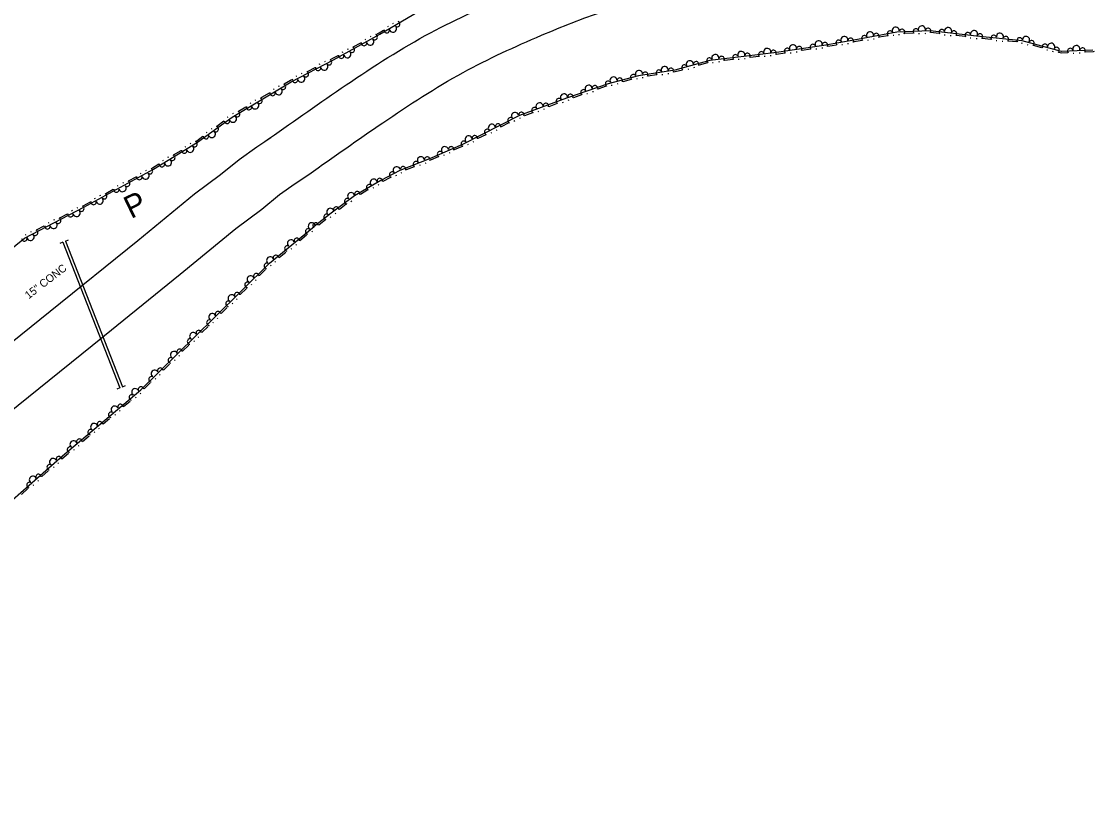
# Model space of a CAD drawing. Extents: x 2030130 to 2036320, y 723205 to 762423.
# Drawn here: x 2033977 to 2034480, y 760652 to 761017 of the extents above; entities that cross this region are included whole.
import ezdxf

# ---------------------------------------------------------------- set-up
doc = ezdxf.new("R2010")
doc.units = 0
for name, color, linetype in [('Draft_Station Labels Major', 7, 'Continuous'), ('Draft_Station Tics Major', 7, 'Continuous'), ('Draft_Station Tics Minor', 7, 'Continuous'), ('Old_Level_26', 7, 'Continuous'), ('Prop Horizontal Alignment Ramp', 7, 'Continuous')]:
    doc.layers.add(name, color=color, linetype=linetype)

msp = doc.modelspace()

# ---------------------------------------------------------------- linework, layer by layer
at = {"layer": 'Draft_Station Labels Major'}
for points in [[(2033869.46, 760774.27), (2033935.13, 760835.34), (2033990.71, 760880.07), (2034032.11, 760913.52), (2034058.88, 760935.52), (2034071.14, 760944.6), (2034079.83, 760951.72), (2034088.18, 760957.58), (2034094.76, 760962.04)], [(2033886.15, 760763.66), (2033955.13, 760819.42), (2034010.47, 760863.96), (2034051.97, 760897.49), (2034078.31, 760919.14), (2034090.56, 760928.21), (2034098.99, 760935.12), (2034106.37, 760940.3), (2034112.77, 760944.64)]]:
    msp.add_lwpolyline(points, dxfattribs=at)
for points in [[(2034092.04, 760960.15), (2034128.02, 760985.27), (2034167.72, 761010.14), (2034207.02, 761028.78), (2034238.75, 761041.08), (2034290.36, 761053.26), (2034339.84, 761057.27), (2034410.92, 761061), (2034496.35, 761063.49), (2034597.04, 761068.5), (2034676.22, 761073.92), (2034760.74, 761078.95), (2034860.07, 761085.08), (2034928.36, 761090.57)], [(2034112.77, 760944.64), (2034147.71, 760969.04), (2034185.56, 760992.74), (2034222.61, 761010.31), (2034251.75, 761021.61), (2034299.66, 761032.92), (2034346.78, 761036.74), (2034417.19, 761040.43), (2034502.59, 761042.92), (2034603.78, 761047.95), (2034683.1, 761053.38), (2034767.53, 761058.4), (2034867.13, 761064.56), (2034935.91, 761070.08)]]:
    msp.add_spline(points, degree=3, dxfattribs=at)
at = {"layer": 'Draft_Station Tics Major'}
for points in [[(2034091.07, 760980.33), (2034104.49, 760988.4), (2034124.48, 760998.73), (2034146.32, 761010.81), (2034166.94, 761022.97)], [(2034149.97, 761014.39), (2034150.32, 761014.6)], [(2034152.44, 761015.85), (2034152.8, 761016.06)], [(2034482.78, 761003.3), (2034468.01, 761002.71), (2034449.36, 761007.75), (2034427.83, 761009.88), (2034406.01, 761012.41), (2034390.26, 761011.73), (2034369.95, 761007.96), (2034355.78, 761005.54), (2034333.42, 761002.12), (2034318.05, 761000.34), (2034302.02, 760998.42), (2034285.55, 760993.78), (2034268.39, 760991.2), (2034254.03, 760987.44), (2034234.41, 760980.56), (2034212.25, 760972.4), (2034185.26, 760958.73), (2034169.68, 760952.03), (2034155.74, 760946.42), (2034146.7, 760941.76), (2034134.36, 760934.57), (2034123.31, 760926.27), (2034115.26, 760920)], [(2034141.81, 761009.72), (2034142.17, 761009.92)], [(2034144.52, 761010.75), (2034145.91, 761011.52), (2034148.06, 761012.79)], [(2034385.97, 761010.1), (2034381.93, 761009.35)], [(2034388.86, 761010.22), (2034388.46, 761010.15)], [(2034391.54, 761010.56), (2034391.12, 761010.54)], [(2034398.07, 761011.25), (2034393.97, 761011.07)], [(2034400.96, 761010.96), (2034400.55, 761010.94)], [(2034403.82, 761011.08), (2034403.42, 761011.06)], [(2034410.21, 761011.09), (2034406.14, 761011.57)], [(2034413.01, 761010.36), (2034412.61, 761010.4)], [(2034415.87, 761010.03), (2034415.46, 761010.07)], [(2034422.43, 761009.68), (2034418.36, 761010.15)], [(2034133.76, 761004.8), (2034137.35, 761006.78)], [(2034139.3, 761008.33), (2034139.66, 761008.53)], [(2034361.74, 761005.72), (2034357.7, 761005.03)], [(2034364.64, 761005.8), (2034364.24, 761005.73)], [(2034367.47, 761006.29), (2034367.06, 761006.22)], [(2034373.87, 761007.85), (2034370.09, 761007.15), (2034369.83, 761007.1)], [(2034376.77, 761007.97), (2034376.37, 761007.9)], [(2034379.59, 761008.5), (2034379.19, 761008.42)], [(2034425.23, 761008.94), (2034424.83, 761008.99)], [(2034428.11, 761008.61), (2034427.69, 761008.65), (2034427.66, 761008.66)], [(2034434.68, 761008.38), (2034430.6, 761008.78)], [(2034437.5, 761007.69), (2034437.09, 761007.73)], [(2034440.35, 761007.41), (2034439.94, 761007.45)], [(2034446.92, 761007.17), (2034442.84, 761007.57)], [(2034449.52, 761006.43), (2034449.13, 761006.54)], [(2034452.29, 761005.69), (2034451.9, 761005.79)], [(2034458.74, 761004.37), (2034454.78, 761005.44)], [(2034123, 760998.88), (2034124.1, 760999.45), (2034126.58, 761000.83)], [(2034128.54, 761002.38), (2034128.89, 761002.57)], [(2034131.05, 761003.77), (2034131.41, 761003.96)], [(2034325.19, 761000.34), (2034321.11, 760999.87)], [(2034328.09, 761000.27), (2034327.68, 761000.22)], [(2034330.94, 761000.6), (2034330.53, 761000.55)], [(2034337.42, 761001.9), (2034333.53, 761001.31), (2034333.33, 761001.29)], [(2034340.32, 761001.93), (2034339.92, 761001.87)], [(2034343.16, 761002.37), (2034342.75, 761002.3)], [(2034349.58, 761003.76), (2034345.53, 761003.14)], [(2034352.48, 761003.79), (2034352.07, 761003.73)], [(2034355.32, 761004.22), (2034354.91, 761004.16)], [(2034461.4, 761003.22), (2034461, 761003.33)], [(2034464.17, 761002.47), (2034463.77, 761002.58)], [(2034470.96, 761002.01), (2034467.92, 761001.88), (2034466.65, 761002.23)], [(2034473.84, 761001.71), (2034473.43, 761001.69)], [(2034476.71, 761001.82), (2034476.3, 761001.81)], [(2034483.43, 761002.63), (2034482.91, 761002.48), (2034479.15, 761002.33)], [(2034112.06, 760993.24), (2034115.71, 760995.12)], [(2034117.71, 760996.61), (2034118.07, 760996.8)], [(2034120.26, 760997.93), (2034120.62, 760998.12)], [(2034294.72, 760995.09), (2034294.32, 760994.98)], [(2034300.92, 760997.26), (2034296.97, 760996.15)], [(2034303.65, 760997.38), (2034303.25, 760997.33)], [(2034306.5, 760997.72), (2034306.1, 760997.67)], [(2034312.97, 760998.91), (2034308.9, 760998.42)], [(2034315.87, 760998.84), (2034315.46, 760998.8)], [(2034318.72, 760999.18), (2034318.31, 760999.14)], [(2034101.19, 760987.38), (2034104.09, 760989.12), (2034104.78, 760989.47)], [(2034106.77, 760990.97), (2034107.14, 760991.16)], [(2034109.32, 760992.29), (2034109.69, 760992.47)], [(2034264.91, 760989.44), (2034260.94, 760988.4)], [(2034267.79, 760989.77), (2034267.39, 760989.66)], [(2034270.48, 760990.27), (2034270.07, 760990.21)], [(2034276.9, 760991.65), (2034272.85, 760991.04)], [(2034279.81, 760991.67), (2034279.4, 760991.61)], [(2034282.64, 760992.1), (2034282.24, 760992.04)], [(2034289.08, 760993.92), (2034285.73, 760992.98), (2034285.01, 760992.87)], [(2034291.96, 760994.31), (2034291.56, 760994.2)], [(2034096.06, 760984.77), (2034096.42, 760984.98)], [(2034098.52, 760986.25), (2034098.87, 760986.46)], [(2034253.1, 760986.24), (2034249.23, 760984.88)], [(2034255.88, 760986.65), (2034255.49, 760986.55)], [(2034258.66, 760987.38), (2034258.26, 760987.27)], [(2033952.27, 760893.42), (2033978.62, 760914.55), (2034006.6, 760929.12), (2034039.46, 760947.07), (2034060.3, 760959.85), (2034076.56, 760971.67), (2034091.07, 760980.33)], [(2034087.46, 760979.61), (2034087.81, 760979.82)], [(2034090.14, 760980.73), (2034090.65, 760981.04)], [(2034090.65, 760981.04), (2034094.17, 760983.15)], [(2034235.43, 760979.61), (2034235.05, 760979.48)], [(2034241.49, 760982.17), (2034237.62, 760980.81)], [(2034244.33, 760982.73), (2034243.95, 760982.6)], [(2034247.04, 760983.68), (2034246.66, 760983.55)], [(2034079.57, 760974.43), (2034083.09, 760976.53)], [(2034085, 760978.14), (2034085.35, 760978.35)], [(2034221.21, 760974.39), (2034220.82, 760974.24)], [(2034223.9, 760975.38), (2034223.52, 760975.24)], [(2034229.92, 760978.03), (2034226.07, 760976.61)], [(2034232.75, 760978.64), (2034232.37, 760978.5)], [(2034069.36, 760967.45), (2034072.68, 760969.86)], [(2034074.42, 760971.64), (2034074.76, 760971.88)], [(2034076.9, 760973.31), (2034077.25, 760973.52)], [(2034209.94, 760969.85), (2034209.57, 760969.67)], [(2034212.5, 760971.15), (2034212.14, 760970.96)], [(2034218.37, 760973.78), (2034214.52, 760972.36)], [(2034064.47, 760964.41), (2034064.81, 760964.65)], [(2034066.79, 760966.09), (2034067.13, 760966.34)], [(2034198.96, 760964.29), (2034198.6, 760964.11)], [(2034201.53, 760965.59), (2034201.16, 760965.4)], [(2034207.19, 760968.92), (2034203.54, 760967.07)], [(2034056.78, 760959.13), (2034057.13, 760959.35)], [(2034059.44, 760960.28), (2034059.84, 760960.53), (2034062.73, 760962.63)], [(2034190.55, 760960.03), (2034190.18, 760959.84)], [(2034196.22, 760963.36), (2034192.56, 760961.51)], [(2034048.95, 760953.85), (2034052.45, 760956)], [(2034054.33, 760957.63), (2034054.68, 760957.85)], [(2034179.32, 760954.83), (2034178.94, 760954.67)], [(2034185.18, 760957.8), (2034181.42, 760956.18)], [(2034187.99, 760958.73), (2034187.62, 760958.55)], [(2034038.48, 760947.47), (2034039.05, 760947.78), (2034041.96, 760949.56)], [(2034043.84, 760951.2), (2034044.19, 760951.41)], [(2034046.29, 760952.7), (2034046.64, 760952.91)], [(2034167.97, 760950.01), (2034167.59, 760949.86)], [(2034173.88, 760952.94), (2034170.12, 760951.32)], [(2034176.68, 760953.7), (2034176.31, 760953.54)], [(2034033.25, 760945.08), (2034033.61, 760945.27)], [(2034035.77, 760946.45), (2034036.13, 760946.65)], [(2034154.09, 760944.18), (2034153.73, 760944)], [(2034156.56, 760945.42), (2034156.26, 760945.3)], [(2034162.49, 760948.25), (2034158.69, 760946.72)], [(2034165.31, 760948.94), (2034164.93, 760948.79)], [(2034022.45, 760939.18), (2034022.81, 760939.37)], [(2034024.97, 760940.55), (2034025.33, 760940.75)], [(2034027.69, 760941.57), (2034031.29, 760943.54)], [(2034145.81, 760939.82), (2034145.45, 760939.61)], [(2034151.35, 760943.23), (2034147.71, 760941.36)], [(2034014.17, 760934.66), (2034014.53, 760934.85)], [(2034016.89, 760935.67), (2034020.49, 760937.64)], [(2034140.64, 760937.28), (2034137.09, 760935.22)], [(2034143.33, 760938.37), (2034142.97, 760938.17)], [(2034003.37, 760928.82), (2034003.73, 760929.01)], [(2034006.11, 760929.79), (2034006.21, 760929.84), (2034009.69, 760931.74)], [(2034011.65, 760933.28), (2034012.01, 760933.48)], [(2034130.45, 760930.6), (2034127.17, 760928.14)], [(2034132.99, 760932), (2034132.66, 760931.76)], [(2034135.18, 760933.63), (2034135.04, 760933.55)], [(2033995.19, 760924.1), (2033998.83, 760926)], [(2034000.82, 760927.5), (2034001.19, 760927.69)], [(2034123.18, 760924.61), (2034122.86, 760924.35)], [(2034125.45, 760926.33), (2034125.12, 760926.09)], [(2033962.23, 760560.87), (2033948, 760582.67), (2033930.82, 760606.44), (2033914.22, 760629.94), (2033898.17, 760653.2), (2033880.46, 760676.52), (2033869.1, 760694.54), (2033868.73, 760704.66), (2033894.67, 760724.53), (2033930.48, 760749.27), (2033951.28, 760770.08), (2033972.88, 760790.96), (2033996.54, 760811.78), (2034033.52, 760843.01), (2034068.11, 760876.92), (2034094.26, 760902.79), (2034115.26, 760920)], [(2033984.28, 760918.42), (2033987.92, 760920.32)], [(2033989.91, 760921.82), (2033990.27, 760922.01)], [(2033992.46, 760923.14), (2033992.82, 760923.33)], [(2034120.67, 760923.16), (2034117.43, 760920.64)], [(2033979, 760916.14), (2033979.36, 760916.33)], [(2033981.54, 760917.46), (2033981.91, 760917.65)], [(2034108.55, 760913.44), (2034111.73, 760916.04)], [(2034114.21, 760917.54), (2034114.52, 760917.8)], [(2034104.37, 760909.48), (2034104.69, 760909.74)], [(2034106.59, 760911.3), (2034106.91, 760911.56)], [(2034098.72, 760905.38), (2034101.89, 760907.98)], [(2034089.42, 760896.85), (2034092.33, 760899.73)], [(2034094.66, 760901.46), (2034094.96, 760901.74)], [(2034096.76, 760903.24), (2034097.08, 760903.5)], [(2034087.66, 760894.53), (2034087.96, 760894.82)], [(2034080.38, 760887.91), (2034083.3, 760890.79)], [(2034085.63, 760892.52), (2034085.92, 760892.81)], [(2034076.59, 760883.58), (2034076.88, 760883.86)], [(2034078.63, 760885.6), (2034078.92, 760885.88)], [(2034071.34, 760878.97), (2034074.26, 760881.85)], [(2034067.54, 760874.64), (2034067.83, 760874.93)], [(2034069.59, 760876.65), (2034069.88, 760876.94)], [(2034062.27, 760870.05), (2034065.2, 760872.92)], [(2034053.19, 760861.15), (2034056.12, 760864.02)], [(2034058.46, 760865.74), (2034058.75, 760866.03)], [(2034060.51, 760867.75), (2034060.8, 760868.04)], [(2034051.43, 760858.85), (2034051.72, 760859.14)], [(2034044.11, 760852.25), (2034047.04, 760855.12)], [(2034049.38, 760856.84), (2034049.67, 760857.13)], [(2034042.35, 760849.95), (2034042.64, 760850.24)], [(2034035.03, 760843.35), (2034037.96, 760846.22)], [(2034040.3, 760847.94), (2034040.59, 760848.23)], [(2034030.94, 760839.22), (2034031.25, 760839.49)], [(2034033.13, 760841.07), (2034033.44, 760841.34)], [(2034025.34, 760835.04), (2034028.48, 760837.68)], [(2034015.63, 760826.83), (2034018.76, 760829.48)], [(2034021.22, 760831.02), (2034021.54, 760831.28)], [(2034023.42, 760832.87), (2034023.73, 760833.13)], [(2034013.7, 760824.67), (2034014.02, 760824.93)], [(2034005.92, 760818.63), (2034009.05, 760821.27)], [(2034011.51, 760822.81), (2034011.82, 760823.08)], [(2034001.8, 760814.61), (2034002.11, 760814.87)], [(2034003.99, 760816.46), (2034004.3, 760816.72)], [(2033994.35, 760808.21), (2033994.66, 760808.48)], [(2033996.23, 760810.42), (2033997.08, 760811.16), (2033999.34, 760813.07)], [(2033986.69, 760802.02), (2033989.77, 760804.73)], [(2033992.19, 760806.32), (2033992.5, 760806.59)], [(2033982.65, 760797.92), (2033982.96, 760798.19)], [(2033984.81, 760799.82), (2033985.11, 760800.09)], [(2033977.14, 760793.62), (2033980.22, 760796.33)]]:
    msp.add_lwpolyline(points, dxfattribs=at)
for centre, radius, start, end in [((2034152.42, 761013.46), 1.69, 196.5046, 44.5771), ((2034154.48, 761015.62), 1.3, 228.9758, 69.7724), ((2034402.1, 761013.06), 1.69, 348.4109, 196.4833), ((2034143.84, 761009.44), 1.3, 227.3824, 68.1789), ((2034149.54, 761012.7), 1.3, 171.3094, 12.1059), ((2034365.51, 761008.03), 1.69, 355.6455, 203.718), ((2034374.93, 761008.88), 1.3, 28.9703, 229.7669), ((2034377.6, 761010.21), 1.69, 356.4991, 204.5716), ((2034380.58, 761009.93), 1.3, 331.3039, 172.1004), ((2034387.03, 761011.13), 1.3, 28.9703, 229.7669), ((2034389.7, 761012.46), 1.69, 356.4991, 204.5716), ((2034392.71, 761011.84), 1.3, 323.2156, 164.0122), ((2034399.27, 761012.12), 1.3, 20.882, 221.6786), ((2034405, 761012.36), 1.3, 323.2156, 164.0122), ((2034411.53, 761011.77), 1.3, 11.8181, 212.6147), ((2034414.47, 761012.25), 1.69, 339.3469, 187.4194), ((2034417.23, 761011.11), 1.3, 314.1516, 154.9482), ((2034423.75, 761010.35), 1.3, 11.8181, 212.6147), ((2034426.69, 761010.83), 1.69, 339.3469, 187.4194), ((2034429.45, 761009.72), 1.3, 315.1383, 155.9349), ((2034435.98, 761009.07), 1.3, 12.8048, 213.6014), ((2034438.92, 761009.61), 1.69, 340.3336, 188.4061), ((2034441.7, 761008.51), 1.3, 315.1383, 155.9349), ((2034451.25, 761008.09), 1.69, 330.8306, 178.9031), ((2034133.08, 761003.48), 1.3, 227.3824, 68.1789), ((2034138.82, 761006.66), 1.3, 169.7159, 10.5125), ((2034141.73, 761007.33), 1.69, 194.9112, 42.9837), ((2034341.23, 761004.14), 1.69, 354.6535, 202.726), ((2034344.19, 761003.77), 1.3, 329.4583, 170.2548), ((2034350.67, 761004.76), 1.3, 27.1247, 227.9213), ((2034353.39, 761006), 1.69, 354.6535, 202.726), ((2034356.35, 761005.64), 1.3, 330.4502, 171.2468), ((2034362.82, 761006.74), 1.3, 28.1167, 228.9132), ((2034368.48, 761007.71), 1.3, 330.4502, 171.2468), ((2034448.23, 761007.87), 1.3, 12.8048, 213.6014), ((2034453.8, 761006.55), 1.3, 305.6353, 146.4319), ((2034460.14, 761004.84), 1.3, 3.3018, 204.0984), ((2034463.12, 761004.88), 1.69, 330.8306, 178.9031), ((2034465.68, 761003.34), 1.3, 305.6353, 146.4319), ((2034474.99, 761003.81), 1.69, 348.2577, 196.3302), ((2034477.89, 761003.1), 1.3, 323.0624, 163.859), ((2034128.05, 761000.7), 1.3, 169.7159, 10.5125), ((2034130.96, 761001.38), 1.69, 194.9112, 42.9837), ((2034301.88, 760998.38), 1.3, 34.1668, 234.9634), ((2034304.63, 760999.56), 1.69, 352.8025, 200.875), ((2034307.58, 760999.09), 1.3, 327.6072, 168.4038), ((2034314.1, 760999.87), 1.3, 25.2737, 226.0702), ((2034316.85, 761001.03), 1.69, 352.8025, 200.875), ((2034319.8, 761000.55), 1.3, 327.3656, 168.1622), ((2034326.32, 761001.3), 1.3, 25.0321, 225.8287), ((2034329.07, 761002.45), 1.69, 352.5609, 200.6334), ((2034332.02, 761001.96), 1.3, 327.3656, 168.1622), ((2034338.51, 761002.9), 1.3, 27.1247, 227.9213), ((2034472.15, 761002.87), 1.3, 20.7289, 221.5254), ((2034117.18, 760994.96), 1.3, 168.0834, 8.8799), ((2034120.11, 760995.54), 1.69, 193.2787, 41.3511), ((2034122.28, 760997.59), 1.3, 225.7498, 66.5464), ((2034280.72, 760993.88), 1.69, 354.5364, 202.6089), ((2034283.68, 760993.5), 1.3, 329.3411, 170.1377), ((2034290.04, 760995.05), 1.3, 34.1668, 234.9634), ((2034292.58, 760996.62), 1.69, 1.6956, 209.7681), ((2034295.57, 760996.6), 1.3, 336.5003, 177.2969), ((2034106.25, 760989.31), 1.3, 168.0834, 8.8799), ((2034109.17, 760989.9), 1.69, 193.2787, 41.3511), ((2034111.35, 760991.95), 1.3, 225.7498, 66.5464), ((2034256.56, 760988.95), 1.69, 0.6277, 208.7002), ((2034259.54, 760988.88), 1.3, 335.4324, 176.229), ((2034265.89, 760990.54), 1.3, 33.0989, 233.8954), ((2034268.55, 760992.05), 1.69, 354.5364, 202.6089), ((2034271.51, 760991.67), 1.3, 329.3411, 170.1377), ((2034278, 760992.64), 1.3, 27.0076, 227.8042), ((2034098.52, 760983.86), 1.69, 196.9924, 45.0649), ((2034100.56, 760986.04), 1.3, 229.4636, 70.2602), ((2034242.38, 760983.35), 1.3, 37.7569, 238.5535), ((2034244.81, 760985.08), 1.69, 5.2857, 213.3582), ((2034247.8, 760985.25), 1.3, 340.0904, 180.887), ((2034253.99, 760987.42), 1.3, 37.7569, 238.5535), ((2034089.5, 760979.39), 1.3, 229.2581, 70.0546), ((2034095.64, 760983.08), 1.3, 171.7971, 12.5937), ((2034230.79, 760979.23), 1.3, 38.6498, 239.4464), ((2034233.2, 760980.99), 1.69, 6.1786, 214.2511), ((2034236.18, 760981.18), 1.3, 340.0904, 180.887), ((2034078.93, 760973.09), 1.3, 229.2581, 70.0546), ((2034084.57, 760976.45), 1.3, 171.5916, 12.3882), ((2034087.46, 760977.22), 1.69, 196.7869, 44.8594), ((2034219.24, 760974.97), 1.3, 38.6498, 239.4464), ((2034221.65, 760976.74), 1.69, 6.1786, 214.2511), ((2034224.63, 760976.96), 1.3, 340.9833, 181.7799), ((2034074.15, 760969.92), 1.3, 176.7926, 17.5892), ((2034076.96, 760970.95), 1.69, 201.9879, 50.0604), ((2034207.92, 760970.21), 1.3, 45.2952, 246.0918), ((2034210.11, 760972.24), 1.69, 12.824, 220.8965), ((2034213.08, 760972.71), 1.3, 340.9833, 181.7799), ((2034067.01, 760963.71), 1.69, 201.9879, 50.0604), ((2034068.85, 760966.06), 1.3, 234.4591, 75.2556), ((2034196.95, 760964.65), 1.3, 45.2952, 246.0918), ((2034199.14, 760966.68), 1.69, 12.824, 220.8965), ((2034202.07, 760967.24), 1.3, 347.6287, 188.4253), ((2034058.82, 760958.94), 1.3, 229.9589, 70.7555), ((2034064.2, 760962.69), 1.3, 176.7926, 17.5892), ((2034185.97, 760959.09), 1.3, 45.2952, 246.0918), ((2034188.16, 760961.12), 1.69, 12.824, 220.8965), ((2034191.09, 760961.68), 1.3, 347.6287, 188.4253), ((2034053.93, 760955.94), 1.3, 172.2925, 13.089), ((2034056.8, 760956.74), 1.69, 197.4877, 45.5602), ((2034174.69, 760954.18), 1.3, 41.7161, 242.5127), ((2034177, 760956.07), 1.69, 9.245, 217.3174), ((2034179.96, 760956.45), 1.3, 344.0497, 184.8463), ((2034043.44, 760949.51), 1.3, 172.2925, 13.089), ((2034046.31, 760950.31), 1.69, 197.4877, 45.5602), ((2034048.33, 760952.51), 1.3, 229.9589, 70.7555), ((2034163.33, 760949.47), 1.3, 40.3537, 241.1503), ((2034165.68, 760951.3), 1.69, 7.8825, 215.955), ((2034168.65, 760951.61), 1.3, 342.6872, 183.4838), ((2034035.67, 760944.06), 1.69, 194.608, 42.6805), ((2034037.8, 760946.16), 1.3, 227.0792, 67.8757), ((2034152.07, 760944.53), 1.3, 45.6841, 246.4806), ((2034154.25, 760946.57), 1.69, 13.2129, 221.2854), ((2034157.24, 760947.02), 1.3, 342.6872, 183.4838), ((2034024.87, 760938.16), 1.69, 194.608, 42.6805), ((2034027, 760940.26), 1.3, 227.0792, 67.8757), ((2034032.76, 760943.41), 1.3, 169.4127, 10.2093), ((2034141.29, 760938.61), 1.3, 48.6495, 249.446), ((2034143.36, 760940.76), 1.69, 16.1783, 224.2508), ((2034146.25, 760941.5), 1.3, 350.983, 191.7796), ((2034016.2, 760934.36), 1.3, 227.0792, 67.8757), ((2034021.96, 760937.51), 1.3, 169.4127, 10.2093), ((2034132.74, 760934.38), 1.69, 22.9078, 230.9803), ((2034135.62, 760935.31), 1.3, 350.983, 191.7796), ((2034005.39, 760928.49), 1.3, 225.9308, 66.7274), ((2034011.16, 760931.61), 1.3, 169.4127, 10.2093), ((2034014.08, 760932.27), 1.69, 194.608, 42.6805), ((2034125.69, 760928.06), 1.3, 357.7125, 198.5091), ((2034130.94, 760932), 1.3, 55.379, 256.1756), ((2033994.48, 760922.81), 1.3, 225.9308, 66.7274), ((2034000.3, 760925.84), 1.3, 168.2644, 9.0609), ((2034003.22, 760926.44), 1.69, 193.4597, 41.5321), ((2034121.13, 760924.57), 1.3, 56.3604, 257.157), ((2034122.9, 760926.99), 1.69, 22.9078, 230.9803), ((2033989.39, 760920.16), 1.3, 168.2644, 9.0609), ((2033992.31, 760920.76), 1.69, 193.4597, 41.5321), ((2034112.47, 760917.71), 1.3, 57.7625, 258.559), ((2034114.18, 760920.16), 1.69, 25.2913, 233.3638), ((2034115.96, 760920.53), 1.3, 358.694, 199.4905), ((2033978.49, 760914.45), 1.3, 179.5059, 20.3024), ((2033981.4, 760915.08), 1.69, 193.4597, 41.5321), ((2033983.57, 760917.13), 1.3, 225.9308, 66.7274), ((2034104.34, 760912.11), 1.69, 25.2913, 233.3638), ((2034107.08, 760913.29), 1.3, 0.096, 200.8926), ((2034102.64, 760909.65), 1.3, 57.7625, 258.559), ((2034094.51, 760904.05), 1.69, 25.2913, 233.3638), ((2034097.25, 760905.23), 1.3, 0.096, 200.8926), ((2034092.92, 760901.47), 1.3, 63.1178, 263.9144), ((2034083.88, 760892.53), 1.3, 63.1178, 263.9144), ((2034085.35, 760895.13), 1.69, 30.6466, 238.7191), ((2034087.97, 760896.56), 1.3, 5.4514, 206.2479), ((2034078.93, 760887.62), 1.3, 5.4514, 206.2479), ((2034074.85, 760883.59), 1.3, 63.1178, 263.9144), ((2034076.31, 760886.19), 1.69, 30.6466, 238.7191), ((2034067.27, 760877.25), 1.69, 30.3937, 238.4662), ((2034069.89, 760878.68), 1.3, 5.4514, 206.2479), ((2034065.8, 760874.66), 1.3, 62.8649, 263.6615), ((2034058.19, 760868.35), 1.69, 30.3937, 238.4662), ((2034060.82, 760869.78), 1.3, 5.1984, 205.995), ((2034056.72, 760865.76), 1.3, 62.8649, 263.6615), ((2034049.12, 760859.45), 1.69, 30.3937, 238.4662), ((2034051.74, 760860.88), 1.3, 5.1984, 205.995), ((2034047.64, 760856.86), 1.3, 62.8649, 263.6615), ((2034038.56, 760847.96), 1.3, 62.8649, 263.6615), ((2034040.04, 760850.55), 1.69, 30.3937, 238.4662), ((2034042.66, 760851.98), 1.3, 5.1984, 205.995), ((2034030.86, 760841.85), 1.69, 26.1528, 234.2253), ((2034033.58, 760843.08), 1.3, 5.1984, 205.995), ((2034029.2, 760839.37), 1.3, 58.624, 259.4206), ((2034021.15, 760833.64), 1.69, 26.1528, 234.2253), ((2034023.87, 760834.87), 1.3, 0.9576, 201.7541), ((2034019.49, 760831.16), 1.3, 58.624, 259.4206), ((2034009.78, 760822.96), 1.3, 58.624, 259.4206), ((2034011.44, 760825.44), 1.69, 26.1528, 234.2253), ((2034014.16, 760826.66), 1.3, 0.9576, 201.7541), ((2034001.73, 760817.23), 1.69, 26.1528, 234.2253), ((2034004.45, 760818.46), 1.3, 0.9576, 201.7541), ((2034000.06, 760814.75), 1.3, 58.624, 259.4206), ((2033992.07, 760808.94), 1.69, 27.2979, 235.3704), ((2033994.77, 760810.22), 1.3, 2.1026, 202.8992), ((2033985.22, 760801.82), 1.3, 2.1026, 202.8992), ((2033990.46, 760806.43), 1.3, 59.7691, 260.5657), ((2033980.91, 760798.03), 1.3, 59.7691, 260.5657), ((2033982.53, 760800.54), 1.69, 27.2979, 235.3704)]:
    msp.add_arc(centre, radius, start, end, dxfattribs=at)
at = {"layer": 'Draft_Station Tics Minor'}
for p, q in [((2033996.73, 760912.63), (2033995.2, 760912.04)), ((2033997.87, 760913.08), (2033999.4, 760913.68)), ((2034023.61, 760843.9), (2034022.08, 760843.3)), ((2034023.61, 760843.9), (2034022.08, 760843.3)), ((2034024.75, 760844.34), (2034026.28, 760844.94)), ((2034024.75, 760844.34), (2034026.28, 760844.94))]:
    msp.add_line(p, q, dxfattribs=at)
for points in [[(2033996.73, 760912.63), (2034023.61, 760843.9)], [(2033997.87, 760913.08), (2034024.75, 760844.34)]]:
    msp.add_lwpolyline(points, dxfattribs=at)

# ---------------------------------------------------------------- texts
at = {"layer": 'Old_Level_26'}
msp.add_text('15" CONC', height=3.691, rotation=37.54, dxfattribs=at).set_placement((2033980.5, 760885.61))
at = {"layer": 'Prop Horizontal Alignment Ramp'}
msp.add_text('P', height=10.66, rotation=25.7434, dxfattribs=at).set_placement((2034028.81, 760923.49))

doc.saveas('drawing.dxf')
